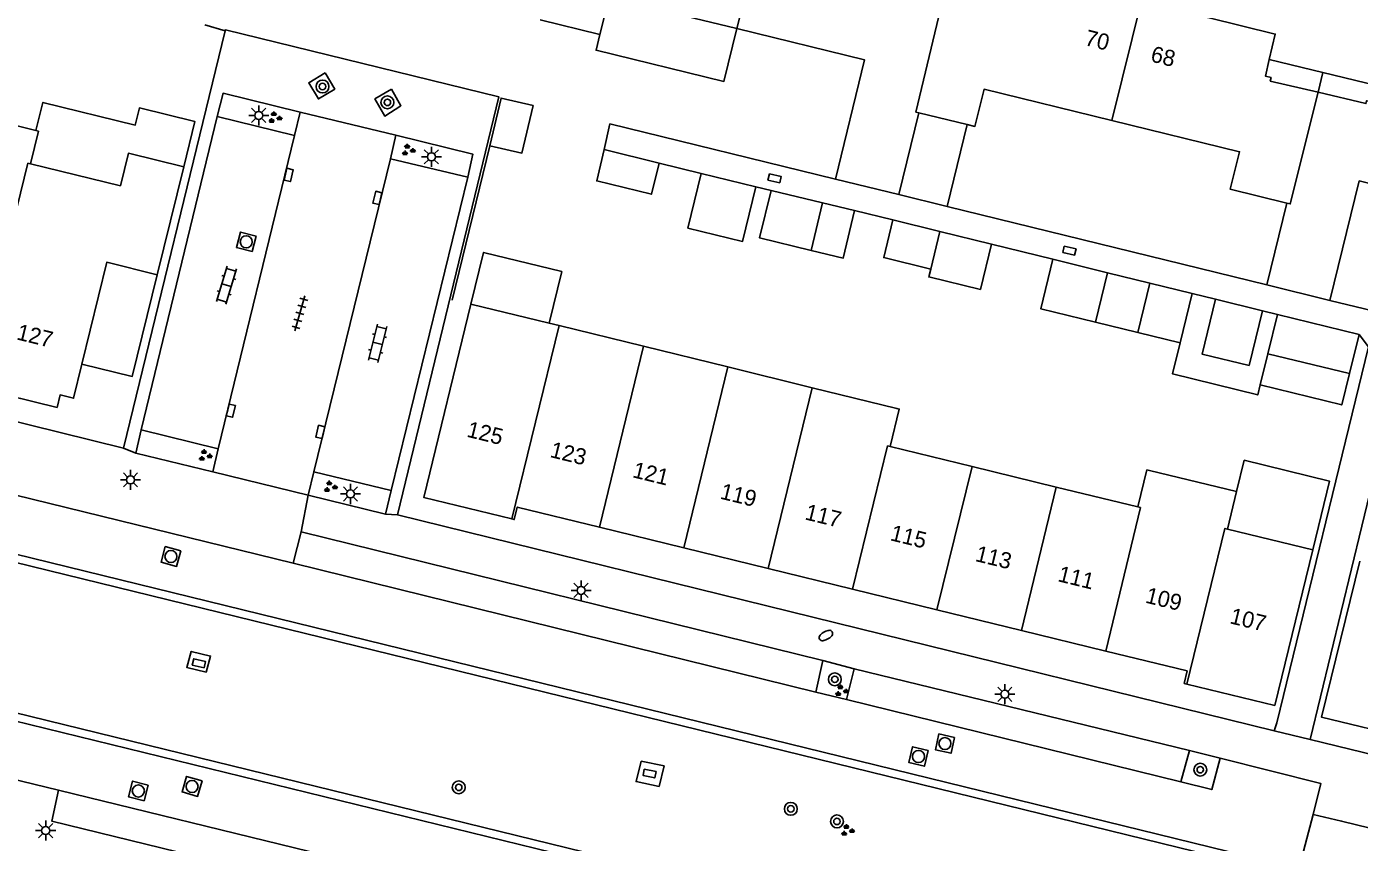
# Model space of a CAD drawing. Extents: x 125000 to 129004, y 397500 to 399008.
# Drawn here: x 126436.9 to 126519.7, y 398569.4 to 398620 of the extents above; entities that cross this region are included whole.
import ezdxf

# ---------------------------------------------------------------- set-up
doc = ezdxf.new("R2010")
doc.units = 0
for name, color, linetype in [('gg-afsc-erfafscheiding', 7, 'Continuous'), ('gg-afsc-hekwerk', 7, 'Continuous'), ('gg-anno-huisnummerreeks BGT', 7, 'Continuous'), ('gg-bbg-bijgebouw', 7, 'Continuous'), ('gg-bbg-gedigitaliseerde bijgebouw', 7, 'Continuous'), ('gg-bbg-hoofdgebouw', 7, 'Continuous'), ('gg-bbg-luifel en loopbrug', 7, 'Continuous'), ('gg-bbg-tussenscheiding', 7, 'Continuous'), ('gg-knt-verharding', 7, 'Continuous'), ('gg-knt-verharding nz', 7, 'Continuous'), ('gt-grn-weggrens', 7, 'Continuous'), ('gt-symb-boom', 7, 'Continuous'), ('gt-symb-brandkraan', 7, 'Continuous'), ('gt-symb-groenvak', 7, 'Continuous'), ('gt-symb-klinker verharding', 7, 'Continuous'), ('gt-symb-kolk', 7, 'Continuous'), ('gt-symb-kolk center center', 7, 'Continuous'), ('gt-symb-lichtmast', 7, 'Continuous'), ('gt-symb-rioolschacht', 7, 'Continuous'), ('gt-symb-tegel verharding', 7, 'Continuous')]:
    doc.layers.add(name, color=color, linetype=linetype)

# ---------------------------------------------------------------- blocks, each defined once
blk = doc.blocks.new('gt0-GRVAK')
at = {"layer": 'gt-symb-groenvak'}
for p, q in [((-0.11, 0.189), (-0.228, 0.24)), ((-0.182, 0.153), (0.088, 0.153)), ((-0.091, 0.211), (-0.156, 0.322)), ((-0.047, 0.214), (-0.047, 0.393)), ((-0.004, 0.211), (0.061, 0.322)), ((0.015, 0.189), (0.133, 0.24)), ((0.262, -0.052), (0.197, 0.059)), ((0.305, -0.049), (0.305, 0.13)), ((0.349, -0.052), (0.414, 0.059)), ((-0.245, -0.228), (-0.363, -0.177)), ((-0.318, -0.264), (-0.047, -0.264)), ((-0.226, -0.206), (-0.291, -0.095)), ((-0.183, -0.203), (-0.183, -0.024)), ((-0.139, -0.206), (-0.074, -0.095)), ((-0.12, -0.228), (-0.002, -0.177)), ((0.243, -0.074), (0.125, -0.023)), ((0.17, -0.11), (0.441, -0.11)), ((0.368, -0.074), (0.486, -0.023))]:
    blk.add_line(p, q, dxfattribs=at)
blk = doc.blocks.new('gt0-LMAST')
at = {"layer": 'gt-symb-lichtmast'}
for p, q in [((-0.182, 0.173), (-0.447, 0.438)), ((-0.005, 0.246), (-0.005, 0.621)), ((0.172, 0.173), (0.437, 0.438)), ((-0.255, -0.004), (-0.63, -0.004)), ((-0.182, -0.181), (-0.447, -0.446)), ((-0.005, -0.254), (-0.005, -0.629)), ((0.437, -0.446), (0.172, -0.181)), ((0.245, -0.004), (0.62, -0.004))]:
    blk.add_line(p, q, dxfattribs=at)
blk.add_circle((-0.005, -0.004), 0.25, dxfattribs=at)
blk = doc.blocks.new('gt0-BOOM')
at = {"layer": 'gt-symb-boom'}
for radius in [0.4, 0.2]:
    blk.add_circle((0, 0), radius, dxfattribs=at)
blk = doc.blocks.new('gt0-KOLKCC')
at = {"layer": 'gt-symb-kolk center center'}
blk.add_lwpolyline([(-0.375, 0.2), (0.375, 0.2), (0.375, -0.2), (-0.375, -0.2)], close=True, dxfattribs=at)
blk = doc.blocks.new('gt0-KL1')
at = {"layer": 'gt-symb-klinker verharding'}
for p, q in [((-1.15, 0.3), (1.15, 0.3)), ((-1, -0.3), (-1, 0.3)), ((-0.5, 0.3), (-0.5, 0.45)), ((0, -0.3), (0, 0.3)), ((0.5, 0.3), (0.5, 0.45)), ((1, -0.3), (1, 0.3)), ((-1.15, -0.3), (1.15, -0.3)), ((-0.5, -0.45), (-0.5, -0.3)), ((0.5, -0.45), (0.5, -0.3))]:
    blk.add_line(p, q, dxfattribs=at)
blk = doc.blocks.new('gt0-TEG1')
at = {"layer": 'gt-symb-tegel verharding'}
for p, q in [((-1.125, 0), (1.125, 0)), ((-0.9, -0.25), (-0.9, 0.25)), ((-0.45, -0.25), (-0.45, 0.25)), ((0, -0.25), (0, 0.25)), ((0.45, -0.25), (0.45, 0.25)), ((0.9, -0.25), (0.9, 0.25))]:
    blk.add_line(p, q, dxfattribs=at)
blk = doc.blocks.new('gt0-RS')
at = {"layer": 'gt-symb-rioolschacht'}
blk.add_lwpolyline([(-0.5, -0.5), (0.5, -0.5), (0.5, 0.5), (-0.5, 0.5)], close=True, dxfattribs=at)
blk.add_circle((0, 0), 0.375, dxfattribs=at)
blk = doc.blocks.new('gt0-KOLK')
at = {"layer": 'gt-symb-kolk'}
blk.add_lwpolyline([(0, 0), (0.375, 0), (0.375, 0.4), (-0.375, 0.4), (-0.375, 0), (0, 0)], dxfattribs=at)
blk = doc.blocks.new('gt0-BR')
at = {"layer": 'gt-symb-brandkraan'}
for centre, radius, start, end in [((-0.244, 0), 0.206, 107.56694, 252.43307), ((0.599, -2.664), 3, 106.89205, 107.56694), ((0, -0.691), 0.938, 73.10799, 106.89205), ((-0.599, -2.664), 3, 72.43309, 73.10799), ((0.244, 0), 0.206, 287.56695, 72.43309), ((0.599, 2.664), 3, 252.43307, 253.10797), ((0, 0.691), 0.938, 253.10797, 286.89206), ((-0.599, 2.664), 3, 286.89206, 287.56695)]:
    blk.add_arc(centre, radius, start, end, dxfattribs=at)

msp = doc.modelspace()

# ---------------------------------------------------------------- linework, layer by layer
at = {"layer": 'gg-afsc-erfafscheiding'}
for p, q in [((126476.219, 398611.58), (126478.842, 398610.938)), ((126482.241, 398610.107), (126483.19, 398609.875)), ((126488.357, 398608.634), (126490.754, 398608.044)), ((126513.975, 398604.009), (126494.119, 398608.882)), ((126496.872, 398606.539), (126500.687, 398605.601)), ((126534.591, 398598.969), (126517.906, 398603.051))]:
    msp.add_line(p, q, dxfattribs=at)
for points in [[(126487.174, 398610.578), (126473.168, 398614.006), (126472.819, 398612.411)], [(126519.71, 398600.927), (126520.306, 398600.163), (126514.596, 398576.815), (126514.448, 398576.329)], [(126516.671, 398575.792), (126522.462, 398599.626), (126523.459, 398600.086), (126526.396, 398599.321)]]:
    msp.add_lwpolyline(points, dxfattribs=at)
at = {"layer": 'gg-afsc-hekwerk'}
for p, q in [((126449.262, 398619.792), (126447.992, 398620.163)), ((126442.945, 398593.869), (126449.262, 398619.792)), ((126465.71, 398612.655), (126463.373, 398603.069))]:
    msp.add_line(p, q, dxfattribs=at)
at = {"layer": 'gg-bbg-bijgebouw'}
for p, q in [((126485.675, 398606.141), (126486.365, 398609.099)), ((126486.365, 398609.099), (126488.357, 398608.634))]:
    msp.add_line(p, q, dxfattribs=at)
for points in [[(126465.71, 398612.655), (126467.701, 398612.191), (126468.392, 398615.148), (126466.4, 398615.613), (126465.71, 398612.655)], [(126488.357, 398608.634), (126487.666, 398605.677), (126485.675, 398606.141)]]:
    msp.add_lwpolyline(points, dxfattribs=at)
at = {"layer": 'gg-bbg-gedigitaliseerde bijgebouw'}
for p, q in [((126472.819, 398612.411), (126476.219, 398611.58)), ((126478.842, 398610.938), (126482.241, 398610.107)), ((126490.754, 398608.044), (126493.668, 398607.328)), ((126493.668, 398607.328), (126496.872, 398606.539)), ((126500.687, 398605.601), (126504.086, 398604.765)), ((126504.086, 398604.765), (126503.337, 398601.7)), ((126506.714, 398604.118), (126505.975, 398601.056)), ((126506.714, 398604.118), (126509.336, 398603.473)), ((126508.599, 398600.422), (126509.336, 398603.473)), ((126510.793, 398603.115), (126513.706, 398602.4)), ((126514.641, 398602.171), (126514.047, 398599.74)), ((126514.641, 398602.171), (126519.71, 398600.927)), ((126505.975, 398601.056), (126508.599, 398600.422)), ((126519.117, 398598.501), (126519.71, 398600.927)), ((126514.047, 398599.74), (126519.117, 398598.501))]:
    msp.add_line(p, q, dxfattribs=at)
for points in [[(126472.819, 398612.411), (126472.344, 398610.468), (126475.744, 398609.638), (126476.219, 398611.58)], [(126478.842, 398610.938), (126478.011, 398607.539), (126481.411, 398606.708), (126482.241, 398610.107)], [(126493.098, 398604.996), (126490.184, 398605.708), (126490.754, 398608.044)], [(126493.098, 398604.996), (126492.979, 398604.51), (126496.185, 398603.727), (126496.872, 398606.539)], [(126503.337, 398601.7), (126499.937, 398602.531), (126500.687, 398605.601)], [(126510.793, 398603.115), (126509.963, 398599.717), (126512.877, 398599.007), (126513.706, 398602.4)]]:
    msp.add_lwpolyline(points, dxfattribs=at)
at = {"layer": 'gg-bbg-hoofdgebouw'}
for p, q in [((126468.826, 398620.462), (126472.548, 398619.553)), ((126434.127, 398614.422), (126437.506, 398613.591)), ((126491.128, 398609.616), (126492.369, 398614.697)), ((126492.369, 398614.697), (126495.361, 398613.966)), ((126446.686, 398611.344), (126445.028, 398604.641)), ((126491.128, 398609.616), (126487.174, 398610.578)), ((126515.217, 398609.094), (126513.975, 398604.009)), ((126517.906, 398603.051), (126513.975, 398604.009)), ((126469.388, 398601.634), (126464.531, 398602.822)), ((126470.007, 398601.482), (126469.388, 398601.634)), ((126475.252, 398600.199), (126470.007, 398601.482)), ((126480.497, 398598.914), (126475.252, 398600.199)), ((126485.742, 398597.628), (126480.497, 398598.914)), ((126490.987, 398596.343), (126485.742, 398597.628)), ((126495.678, 398592.73), (126490.583, 398593.971)), ((126500.885, 398591.461), (126495.678, 398592.73)), ((126512.106, 398591.182), (126506.684, 398592.489)), ((126505.977, 398590.221), (126500.885, 398591.461)), ((126511.543, 398588.849), (126512.106, 398591.182)), ((126472.511, 398588.965), (126477.758, 398587.683)), ((126516.836, 398587.556), (126511.543, 398588.849)), ((126477.758, 398587.683), (126483.002, 398586.401)), ((126483.002, 398586.401), (126488.249, 398585.119)), ((126488.249, 398585.119), (126493.475, 398583.842)), ((126493.475, 398583.842), (126498.739, 398582.556)), ((126498.739, 398582.556), (126503.976, 398581.276))]:
    msp.add_line(p, q, dxfattribs=at)
for points in [[(126514.133, 398618.005), (126514.505, 398619.582), (126510.307, 398620.608), (126510.545, 398621.582), (126506.434, 398622.598)], [(126472.548, 398619.553), (126473.113, 398621.866), (126481.049, 398619.928)], [(126481.049, 398619.928), (126488.984, 398617.99), (126487.174, 398610.578)], [(126517.168, 398615.97), (126514.197, 398616.67), (126514.249, 398616.893), (126513.891, 398616.977), (126514.133, 398618.005)], [(126495.361, 398613.966), (126495.847, 398613.847), (126496.412, 398616.159), (126504.349, 398614.22)], [(126520.797, 398616.383), (126520.55, 398615.362), (126520.179, 398615.448), (126520.138, 398615.27), (126517.168, 398615.97)], [(126437.506, 398613.591), (126437.661, 398613.553), (126437.156, 398611.532)], [(126504.349, 398614.22), (126512.285, 398612.281), (126511.715, 398609.95), (126515.217, 398609.094)], [(126437.156, 398611.532), (126442.751, 398610.164), (126443.245, 398612.185), (126446.686, 398611.344)], [(126517.906, 398603.051), (126519.726, 398610.471), (126527.656, 398608.526)], [(126440.359, 398599.089), (126439.843, 398596.973), (126439.008, 398597.177), (126438.818, 398596.4), (126434.272, 398597.516), (126434.463, 398598.293), (126433.628, 398598.498), (126435.702, 398606.948)], [(126445.028, 398604.641), (126441.902, 398605.414), (126440.359, 398599.089)], [(126464.531, 398602.822), (126461.597, 398590.815), (126467.069, 398589.482)], [(126490.583, 398593.971), (126491.143, 398596.305), (126490.987, 398596.343)], [(126506.684, 398592.489), (126506.528, 398592.527), (126505.977, 398590.221)], [(126467.069, 398589.482), (126467.225, 398589.444), (126467.412, 398590.211), (126472.511, 398588.965)], [(126509.003, 398579.225), (126514.477, 398577.898), (126516.836, 398587.556)], [(126519.752, 398586.855), (126517.375, 398577.173), (126522.858, 398575.839)], [(126503.976, 398581.276), (126509.026, 398580.042), (126508.849, 398579.262), (126509.003, 398579.225)]]:
    msp.add_lwpolyline(points, dxfattribs=at)
at = {"layer": 'gg-bbg-luifel en loopbrug'}
for p, q in [((126517.466, 398617.194), (126514.133, 398618.005)), ((126517.168, 398615.97), (126517.466, 398617.194)), ((126520.797, 398616.383), (126517.466, 398617.194)), ((126495.361, 398613.966), (126494.119, 398608.882)), ((126483.19, 398609.875), (126486.365, 398609.099)), ((126494.119, 398608.882), (126491.128, 398609.616)), ((126504.086, 398604.765), (126506.714, 398604.118)), ((126509.336, 398603.473), (126510.793, 398603.115)), ((126513.706, 398602.4), (126514.641, 398602.171)), ((126505.975, 398601.056), (126503.337, 398601.7)), ((126513.574, 398597.802), (126514.047, 398599.74))]:
    msp.add_line(p, q, dxfattribs=at)
for points in [[(126472.548, 398619.553), (126472.311, 398618.582), (126480.247, 398616.643), (126481.049, 398619.928)], [(126437.506, 398613.591), (126437.934, 398615.339), (126443.673, 398613.936), (126443.934, 398615.005), (126447.375, 398614.163), (126446.686, 398611.344)], [(126485.675, 398606.141), (126482.469, 398606.924), (126483.19, 398609.875)], [(126464.531, 398602.822), (126465.314, 398606.028), (126470.171, 398604.841), (126469.388, 398601.634)], [(126445.028, 398604.641), (126443.488, 398598.326), (126440.359, 398599.089)], [(126508.599, 398600.422), (126508.124, 398598.479), (126513.423, 398597.185), (126513.574, 398597.802)], [(126519.117, 398598.501), (126518.641, 398596.559), (126513.574, 398597.802)], [(126512.106, 398591.182), (126512.583, 398593.124), (126517.883, 398591.823), (126516.836, 398587.556)]]:
    msp.add_lwpolyline(points, dxfattribs=at)
at = {"layer": 'gg-bbg-tussenscheiding'}
for p, q in [((126483.129, 398628.28), (126481.049, 398619.928)), ((126506.434, 398622.598), (126504.349, 398614.22)), ((126493.668, 398607.328), (126493.098, 398604.996)), ((126470.007, 398601.482), (126467.069, 398589.482)), ((126475.252, 398600.199), (126472.511, 398588.965)), ((126477.758, 398587.683), (126480.497, 398598.914)), ((126485.742, 398597.628), (126483.002, 398586.401)), ((126495.678, 398592.73), (126493.475, 398583.842)), ((126500.885, 398591.461), (126498.739, 398582.556))]:
    msp.add_line(p, q, dxfattribs=at)
for points in [[(126493.835, 398621.65), (126492.183, 398614.742), (126492.369, 398614.697)], [(126517.168, 398615.97), (126515.441, 398609.039), (126515.217, 398609.094)], [(126435.702, 398606.948), (126435.857, 398606.91), (126437.007, 398611.569), (126437.156, 398611.532)], [(126488.249, 398585.119), (126490.418, 398594.011), (126490.583, 398593.971)], [(126505.977, 398590.221), (126506.127, 398590.184), (126503.976, 398581.276)], [(126511.543, 398588.849), (126511.377, 398588.89), (126509.003, 398579.225)]]:
    msp.add_lwpolyline(points, dxfattribs=at)
at = {"layer": 'gg-knt-verharding'}
for p, q in [((126444.038, 398595.019), (126448.774, 398614.474)), ((126448.774, 398614.474), (126453.576, 398613.292)), ((126453.915, 398614.73), (126453.576, 398613.292)), ((126453.576, 398613.292), (126448.832, 398593.838)), ((126459.872, 398613.3), (126459.527, 398611.844)), ((126459.527, 398611.844), (126454.779, 398592.398)), ((126459.527, 398611.844), (126464.33, 398610.703)), ((126459.578, 398591.236), (126464.33, 398610.703)), ((126442.945, 398593.869), (126405.897, 398603.002)), ((126517.51, 398566.878), (126403.967, 398594.687)), ((126443.713, 398593.571), (126444.038, 398595.019)), ((126444.038, 398595.019), (126448.832, 398593.838)), ((126515.98, 398567.758), (126408.971, 398593.976)), ((126448.832, 398593.838), (126448.503, 398592.408)), ((126453.487, 398586.734), (126428.052, 398592.957)), ((126448.503, 398592.408), (126443.713, 398593.571)), ((126454.779, 398592.398), (126454.411, 398590.963)), ((126459.578, 398591.236), (126454.779, 398592.398)), ((126459.217, 398589.781), (126459.578, 398591.236)), ((126454.411, 398590.963), (126459.217, 398589.781)), ((126514.448, 398576.329), (126459.973, 398589.732)), ((126453.984, 398588.672), (126453.487, 398586.734)), ((126486.403, 398580.681), (126453.984, 398588.672)), ((126513.861, 398558.458), (126401.799, 398585.868)), ((126513.742, 398557.972), (126406.588, 398584.182)), ((126485.962, 398578.719), (126486.403, 398580.681)), ((126486.403, 398580.681), (126488.333, 398580.165)), ((126488.333, 398580.165), (126487.861, 398578.258)), ((126509.168, 398575.107), (126488.333, 398580.165)), ((126487.861, 398578.258), (126485.962, 398578.719)), ((126423.405, 398576.453), (126438.905, 398572.629)), ((126618.701, 398550.799), (126516.671, 398575.792)), ((126509.168, 398575.107), (126508.648, 398573.148)), ((126511.084, 398574.625), (126509.168, 398575.107)), ((126515.98, 398567.758), (126516.855, 398571.13))]:
    msp.add_line(p, q, dxfattribs=at)
for points in [[(126459.973, 398589.732), (126466.272, 398615.684), (126449.275, 398619.844), (126449.262, 398619.792)], [(126455.465, 398617.186), (126454.453, 398616.567), (126455.055, 398615.558), (126456.068, 398616.169), (126455.465, 398617.186)], [(126459.589, 398616.168), (126460.177, 398615.136), (126459.178, 398614.491), (126458.568, 398615.557), (126459.589, 398616.168)], [(126448.774, 398614.474), (126449.133, 398615.91), (126453.915, 398614.73)], [(126464.33, 398610.703), (126464.658, 398612.126), (126459.872, 398613.3)], [(126448.074, 398579.97), (126446.878, 398580.26), (126447.156, 398581.258), (126448.352, 398580.968), (126448.074, 398579.97)], [(126508.648, 398573.148), (126510.565, 398572.677), (126511.084, 398574.625)], [(126516.855, 398571.13), (126517.336, 398573.054), (126511.084, 398574.625)], [(126475.099, 398574.434), (126474.792, 398573.168), (126476.227, 398572.875), (126476.534, 398574.142), (126475.099, 398574.434)], [(126454.065, 398566.907), (126438.487, 398570.714), (126438.905, 398572.629)], [(126532.704, 398567.274), (126518.629, 398570.719), (126516.855, 398571.13)]]:
    msp.add_lwpolyline(points, dxfattribs=at)
at = {"layer": 'gg-knt-verharding nz'}
for p, q in [((126453.487, 398586.734), (126485.962, 398578.719)), ((126487.861, 398578.258), (126508.648, 398573.148)), ((126438.905, 398572.629), (126454.51, 398568.819))]:
    msp.add_line(p, q, dxfattribs=at)
at = {"layer": 'gt-grn-weggrens'}
for p, q in [((126453.915, 398614.73), (126459.872, 398613.3)), ((126442.945, 398593.869), (126443.713, 398593.571)), ((126448.503, 398592.408), (126454.411, 398590.963)), ((126454.411, 398590.963), (126453.984, 398588.672)), ((126459.217, 398589.781), (126459.973, 398589.732)), ((126514.448, 398576.329), (126516.671, 398575.792))]:
    msp.add_line(p, q, dxfattribs=at)

# ---------------------------------------------------------------- block references
at = {"layer": 'gt-symb-boom'}
for p in [(126455.31, 398616.33), (126459.342, 398615.345), (126487.14, 398579.518), (126509.847, 398573.908), (126463.774, 398572.811), (126484.405, 398571.476), (126487.274, 398570.696)]:
    msp.add_blockref('gt0-BOOM', p, dxfattribs=at)
at = {"layer": 'gt-symb-brandkraan', "rotation": -150.8451896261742}
msp.add_blockref('gt0-BR', (126486.588, 398582.241), dxfattribs=at)
at = {"layer": 'gt-symb-groenvak'}
for p in [(126452.332, 398614.389), (126460.618, 398612.378), (126447.996, 398593.409), (126455.776, 398591.47), (126487.534, 398578.807), (126487.906, 398570.132)]:
    msp.add_blockref('gt0-GRVAK', p, dxfattribs=at)
at = {"layer": 'gt-symb-klinker verharding'}
for p, rotation in [((126449.343, 398603.993), -106.5511367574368), ((126458.735, 398600.377), 75.88039706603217)]:
    msp.add_blockref('gt0-KL1', p, dxfattribs=dict(at, rotation=rotation))
at = {"layer": 'gt-symb-kolk'}
for p, rotation in [((126453.01, 398610.888), -103.29958432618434), ((126458.912, 398609.362), 76.1165819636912), ((126449.421, 398596.249), -103.77214543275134), ((126455.369, 398594.835), 76.29711003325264)]:
    msp.add_blockref('gt0-KOLK', p, dxfattribs=dict(at, rotation=rotation))
at = {"layer": 'gt-symb-kolk center center'}
for p, rotation in [((126483.396, 398610.635), -13.007504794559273), ((126501.72, 398606.144), -12.715336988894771), ((126447.628, 398580.517), 167.58922528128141), ((126475.631, 398573.669), -11.882758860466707)]:
    msp.add_blockref('gt0-KOLKCC', p, dxfattribs=dict(at, rotation=rotation))
at = {"layer": 'gt-symb-lichtmast'}
for p in [(126451.354, 398614.537), (126462.083, 398611.967), (126443.384, 398591.91), (126457.052, 398591.035), (126471.381, 398585.044), (126497.712, 398578.599), (126438.115, 398570.131)]:
    msp.add_blockref('gt0-LMAST', p, dxfattribs=at)
at = {"layer": 'gt-symb-rioolschacht'}
for p, rotation in [((126450.572, 398606.685), 75.75525752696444), ((126445.893, 398587.149), 164.81021283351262), ((126493.983, 398575.529), 167.40904938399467), ((126492.338, 398574.728), 166.5889281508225), ((126443.867, 398572.587), 165.10181274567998), ((126447.203, 398572.869), 163.86579540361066)]:
    msp.add_blockref('gt0-RS', p, dxfattribs=dict(at, rotation=rotation))
at = {"layer": 'gt-symb-tegel verharding', "rotation": 74.10181291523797}
msp.add_blockref('gt0-TEG1', (126453.901, 398602.246), dxfattribs=at)

# ---------------------------------------------------------------- texts
at = {"layer": 'gg-anno-huisnummerreeks BGT'}
for s, rotation, p in [('70', 346.1, (126502.61, 398618.908)), ('68', 346.1, (126506.707, 398617.896)), ('127', 346.2, (126436.248, 398600.635)), ('125', 346.3, (126464.22, 398594.593)), ('123', 346.3, (126469.394, 398593.329)), ('121', 346.3, (126474.522, 398592.076)), ('119', 346.3, (126479.963, 398590.746)), ('117', 346.3, (126485.231, 398589.458)), ('115', 346.3, (126490.531, 398588.163)), ('113', 346.3, (126495.815, 398586.872)), ('111', 346.3, (126500.945, 398585.619)), ('109', 346.3, (126506.385, 398584.289)), ('107', 346.3, (126511.627, 398583.008))]:
    msp.add_text(s, height=1, rotation=rotation, dxfattribs=at).set_placement(p)

doc.saveas('drawing.dxf')
